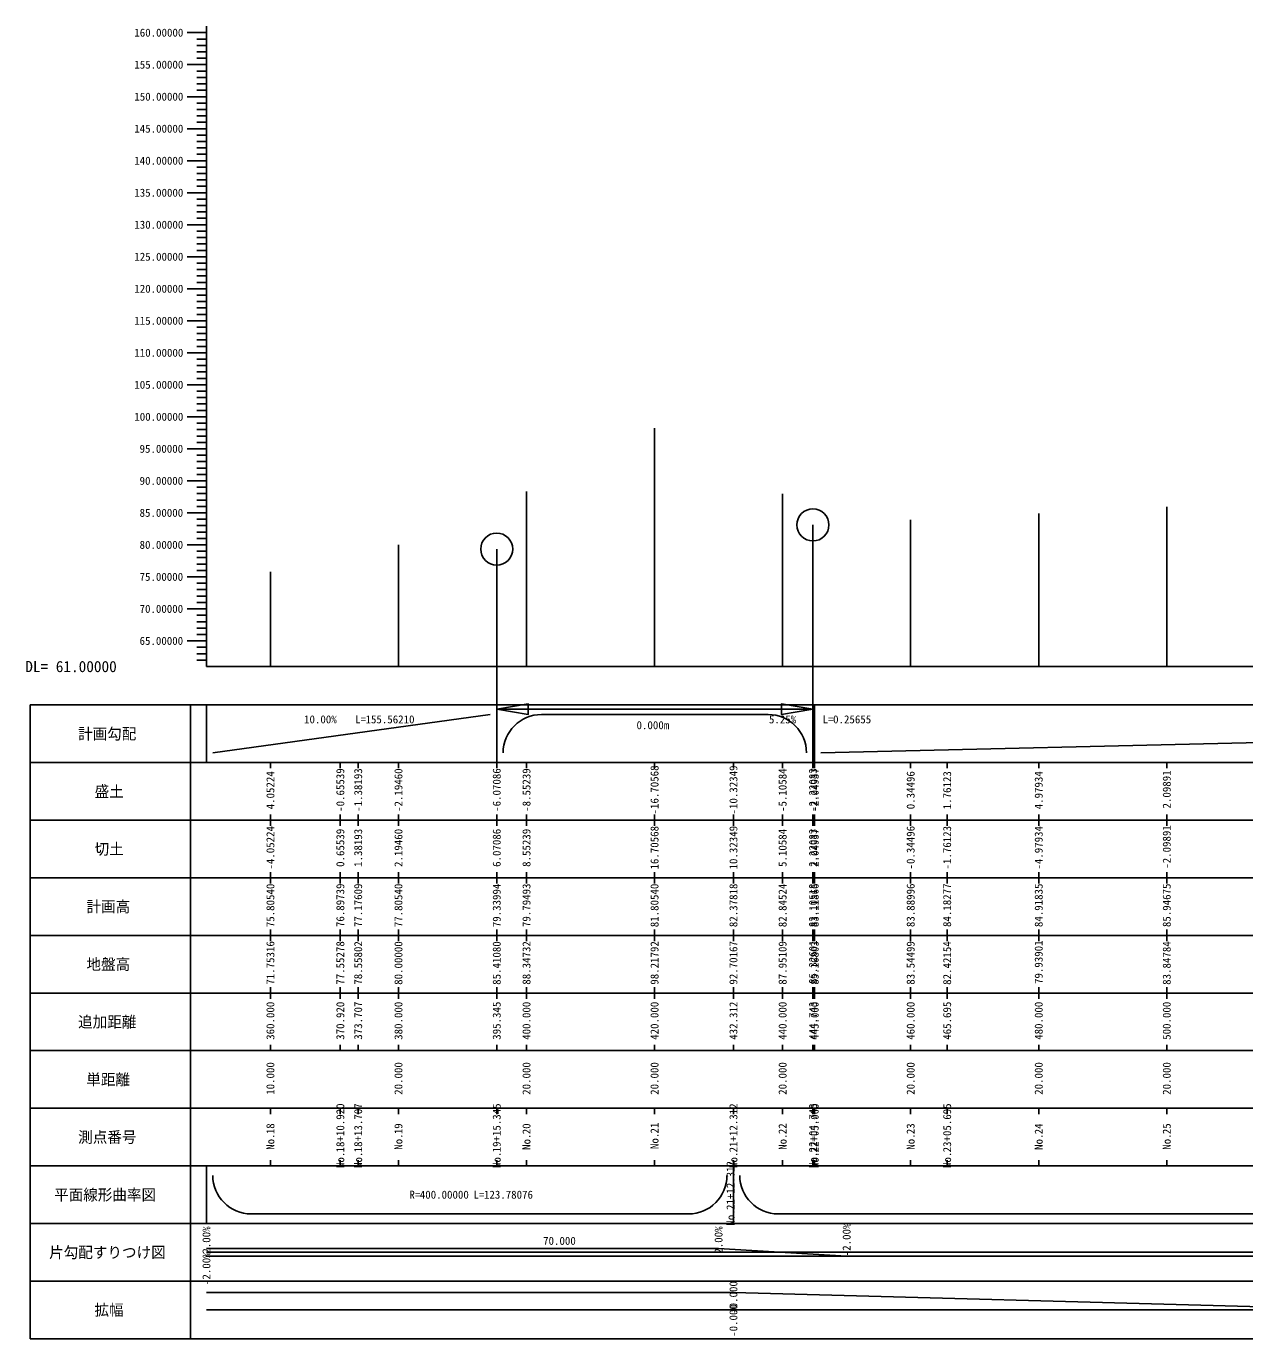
# Model space of a CAD drawing. Extents: x 322 to 703, y -44 to 161.
# Drawn here: x 321.9 to 512.2, y -44 to 161 of the extents above; entities that cross this region are included whole.
import ezdxf

# ---------------------------------------------------------------- set-up
doc = ezdxf.new("R2010")
doc.units = 0
for name, color, linetype in [('Default', 7, 'Continuous'), ('設計図面_縦断図_グリッド', 7, 'Continuous'), ('設計図面_縦断図_テキスト', 7, 'Continuous')]:
    doc.layers.add(name, color=color, linetype=linetype)

msp = doc.modelspace()

# ---------------------------------------------------------------- linework, layer by layer
at = {"layer": 'Default'}
for p, q in [((444.74, 83.11), (444.74, 54.34)), ((395.35, 79.34), (395.35, 54.34)), ((395.35, 56.84), (395.35, 51.84)), ((444.74, 51.84), (444.74, 56.84)), ((350, 55), (350, 46)), ((395.35, 55), (395.35, 46)), ((395.35, 55), (395.35, 46)), ((395.35, 54.34), (444.74, 54.34)), ((444.74, 55), (444.74, 46)), ((444.74, 55), (444.74, 46)), ((445, 55), (445, 46)), ((445, 55), (445, 46)), ((350, -17), (350, -26)), ((432.31, -17), (432.31, -26)), ((432.31, -17), (432.31, -26)), ((350, -29.9), (430, -29.9)), ((430, -29.9), (450, -31.1)), ((450, -31.1), (700, -31.1))]:
    msp.add_line(p, q, dxfattribs=at)
for points in [[(395.35, 54.34), (400.28, 55.16), (400.28, 53.52)], [(444.74, 54.34), (439.81, 53.52), (439.81, 55.16)]]:
    msp.add_lwpolyline(points, close=True, dxfattribs=at)
for centre in [(444.74, 83.11), (395.35, 79.34)]:
    msp.add_circle(centre, 2.5, dxfattribs=at)
at = {"layer": '設計図面_縦断図_グリッド'}
for p, q in [((350, 160), (347, 160)), ((350, 61), (350, 161)), ((350, 159), (348.5, 159)), ((350, 158), (348.5, 158)), ((350, 157), (348.5, 157)), ((350, 156), (348.5, 156)), ((350, 155), (347, 155)), ((350, 154), (348.5, 154)), ((350, 153), (348.5, 153)), ((350, 152), (348.5, 152)), ((350, 150), (347, 150)), ((350, 151), (348.5, 151)), ((350, 149), (348.5, 149)), ((350, 148), (348.5, 148)), ((350, 147), (348.5, 147)), ((350, 146), (348.5, 146)), ((350, 145), (347, 145)), ((350, 144), (348.5, 144)), ((350, 143), (348.5, 143)), ((350, 142), (348.5, 142)), ((350, 140), (347, 140)), ((350, 141), (348.5, 141)), ((350, 139), (348.5, 139)), ((350, 138), (348.5, 138)), ((350, 137), (348.5, 137)), ((350, 136), (348.5, 136)), ((350, 135), (347, 135)), ((350, 134), (348.5, 134)), ((350, 133), (348.5, 133)), ((350, 132), (348.5, 132)), ((350, 130), (347, 130)), ((350, 131), (348.5, 131)), ((350, 129), (348.5, 129)), ((350, 128), (348.5, 128)), ((350, 127), (348.5, 127)), ((350, 126), (348.5, 126)), ((350, 125), (347, 125)), ((350, 124), (348.5, 124)), ((350, 123), (348.5, 123)), ((350, 122), (348.5, 122)), ((350, 121), (348.5, 121)), ((350, 120), (347, 120)), ((350, 119), (348.5, 119)), ((350, 118), (348.5, 118)), ((350, 117), (348.5, 117)), ((350, 115), (347, 115)), ((350, 116), (348.5, 116)), ((350, 114), (348.5, 114)), ((350, 113), (348.5, 113)), ((350, 112), (348.5, 112)), ((350, 111), (348.5, 111)), ((350, 110), (347, 110)), ((350, 109), (348.5, 109)), ((350, 108), (348.5, 108)), ((350, 107), (348.5, 107)), ((350, 105), (347, 105)), ((350, 106), (348.5, 106)), ((350, 104), (348.5, 104)), ((350, 103), (348.5, 103)), ((350, 102), (348.5, 102)), ((350, 101), (348.5, 101)), ((350, 100), (347, 100)), ((350, 99), (348.5, 99)), ((350, 98), (348.5, 98)), ((350, 97), (348.5, 97)), ((420, 61), (420, 98.23)), ((350, 95), (347, 95)), ((350, 96), (348.5, 96)), ((350, 94), (348.5, 94)), ((350, 93), (348.5, 93)), ((350, 92), (348.5, 92)), ((350, 91), (348.5, 91)), ((350, 90), (347, 90)), ((350, 89), (348.5, 89)), ((400, 61), (400, 88.35)), ((350, 88), (348.5, 88)), ((350, 87), (348.5, 87)), ((440, 61), (440, 87.96)), ((350, 85), (347, 85)), ((350, 86), (348.5, 86)), ((480, 61), (480, 84.92)), ((500, 61), (500, 85.95)), ((350, 84), (348.5, 84)), ((350, 83), (348.5, 83)), ((350, 82), (348.5, 82)), ((460, 61), (460, 83.89)), ((350, 80), (347, 80)), ((350, 81), (348.5, 81)), ((380, 61), (380, 80)), ((350, 79), (348.5, 79)), ((350, 78), (348.5, 78)), ((350, 77), (348.5, 77)), ((350, 76), (348.5, 76)), ((350, 75), (347, 75)), ((350, 74), (348.5, 74)), ((360, 61), (360, 75.81)), ((350, 73), (348.5, 73)), ((350, 72), (348.5, 72)), ((350, 70), (347, 70)), ((350, 71), (348.5, 71)), ((350, 69), (348.5, 69)), ((350, 68), (348.5, 68)), ((350, 67), (348.5, 67)), ((350, 66), (348.5, 66)), ((350, 65), (347, 65)), ((350, 64), (348.5, 64)), ((350, 63), (348.5, 63)), ((350, 62), (348.5, 62)), ((350, 61), (700, 61)), ((322.5, 55), (322.5, 46)), ((702.5, 55), (322.5, 55)), ((347.5, 55), (347.5, 46)), ((351, 47.5), (394.35, 53.5)), ((402.35, 53.5), (437.74, 53.5)), ((446, 47.5), (699, 53.5)), ((322.5, 46), (702.5, 46)), ((322.5, 46), (322.5, 37)), ((702.5, 46), (322.5, 46)), ((347.5, 46), (347.5, 37)), ((360, 46), (360, 45.1)), ((370.92, 46), (370.92, 45.1)), ((373.71, 46), (373.71, 45.1)), ((380, 46), (380, 45.1)), ((395.35, 46), (395.35, 45.1)), ((400, 46), (400, 45.1)), ((420, 46), (420, 45.1)), ((432.31, 46), (432.31, 45.1)), ((440, 46), (440, 45.1)), ((444.74, 46), (444.74, 45.1)), ((445, 46), (445, 45.1)), ((460, 46), (460, 45.1)), ((465.69, 46), (465.69, 45.1)), ((480, 46), (480, 45.1)), ((500, 46), (500, 45.1)), ((322.5, 37), (702.5, 37)), ((322.5, 37), (322.5, 28)), ((702.5, 37), (322.5, 37)), ((347.5, 37), (347.5, 28)), ((360, 37), (360, 37.9)), ((360, 37), (360, 36.1)), ((370.92, 37), (370.92, 37.9)), ((370.92, 37), (370.92, 36.1)), ((373.71, 37), (373.71, 37.9)), ((373.71, 37), (373.71, 36.1)), ((380, 37), (380, 37.9)), ((380, 37), (380, 36.1)), ((395.35, 37), (395.35, 37.9)), ((395.35, 37), (395.35, 36.1)), ((400, 37), (400, 37.9)), ((400, 37), (400, 36.1)), ((420, 37), (420, 37.9)), ((420, 37), (420, 36.1)), ((432.31, 37), (432.31, 37.9)), ((432.31, 37), (432.31, 36.1)), ((440, 37), (440, 37.9)), ((440, 37), (440, 36.1)), ((444.74, 37), (444.74, 37.9)), ((444.74, 37), (444.74, 36.1)), ((445, 37), (445, 37.9)), ((445, 37), (445, 36.1)), ((460, 37), (460, 37.9)), ((460, 37), (460, 36.1)), ((465.69, 37), (465.69, 37.9)), ((465.69, 37), (465.69, 36.1)), ((480, 37), (480, 37.9)), ((480, 37), (480, 36.1)), ((500, 37), (500, 37.9)), ((500, 37), (500, 36.1)), ((360, 28), (360, 28.9)), ((370.92, 28), (370.92, 28.9)), ((373.71, 28), (373.71, 28.9)), ((380, 28), (380, 28.9)), ((395.35, 28), (395.35, 28.9)), ((400, 28), (400, 28.9)), ((420, 28), (420, 28.9)), ((432.31, 28), (432.31, 28.9)), ((440, 28), (440, 28.9)), ((444.74, 28), (444.74, 28.9)), ((445, 28), (445, 28.9)), ((460, 28), (460, 28.9)), ((465.69, 28), (465.69, 28.9)), ((480, 28), (480, 28.9)), ((500, 28), (500, 28.9)), ((322.5, 28), (702.5, 28)), ((322.5, 28), (322.5, 19)), ((702.5, 28), (322.5, 28)), ((347.5, 28), (347.5, 19)), ((360, 28), (360, 27.1)), ((370.92, 28), (370.92, 27.1)), ((373.71, 28), (373.71, 27.1)), ((380, 28), (380, 27.1)), ((395.35, 28), (395.35, 27.1)), ((400, 28), (400, 27.1)), ((420, 28), (420, 27.1)), ((432.31, 28), (432.31, 27.1)), ((440, 28), (440, 27.1)), ((444.74, 28), (444.74, 27.1)), ((445, 28), (445, 27.1)), ((460, 28), (460, 27.1)), ((465.69, 28), (465.69, 27.1)), ((480, 28), (480, 27.1)), ((500, 28), (500, 27.1)), ((322.5, 19), (702.5, 19)), ((322.5, 19), (322.5, 10)), ((702.5, 19), (322.5, 19)), ((347.5, 19), (347.5, 10)), ((360, 19), (360, 19.9)), ((360, 19), (360, 18.1)), ((370.92, 19), (370.92, 19.9)), ((370.92, 19), (370.92, 18.1)), ((373.71, 19), (373.71, 19.9)), ((373.71, 19), (373.71, 18.1)), ((380, 19), (380, 19.9)), ((380, 19), (380, 18.1)), ((395.35, 19), (395.35, 19.9)), ((395.35, 19), (395.35, 18.1)), ((400, 19), (400, 19.9)), ((400, 19), (400, 18.1)), ((420, 19), (420, 19.9)), ((420, 19), (420, 18.1)), ((432.31, 19), (432.31, 19.9)), ((432.31, 19), (432.31, 18.1)), ((440, 19), (440, 19.9)), ((440, 19), (440, 18.1)), ((444.74, 19), (444.74, 19.9)), ((444.74, 19), (444.74, 18.1)), ((445, 19), (445, 19.9)), ((445, 19), (445, 18.1)), ((460, 19), (460, 19.9)), ((460, 19), (460, 18.1)), ((465.69, 19), (465.69, 19.9)), ((465.69, 19), (465.69, 18.1)), ((480, 19), (480, 19.9)), ((480, 19), (480, 18.1)), ((500, 19), (500, 19.9)), ((500, 19), (500, 18.1)), ((360, 10), (360, 10.9)), ((370.92, 10), (370.92, 10.9)), ((373.71, 10), (373.71, 10.9)), ((380, 10), (380, 10.9)), ((395.35, 10), (395.35, 10.9)), ((400, 10), (400, 10.9)), ((420, 10), (420, 10.9)), ((432.31, 10), (432.31, 10.9)), ((440, 10), (440, 10.9)), ((444.74, 10), (444.74, 10.9)), ((445, 10), (445, 10.9)), ((460, 10), (460, 10.9)), ((465.69, 10), (465.69, 10.9)), ((480, 10), (480, 10.9)), ((500, 10), (500, 10.9)), ((322.5, 10), (702.5, 10)), ((322.5, 10), (322.5, 1)), ((702.5, 10), (322.5, 10)), ((347.5, 10), (347.5, 1)), ((360, 10), (360, 9.1)), ((370.92, 10), (370.92, 9.1)), ((373.71, 10), (373.71, 9.1)), ((380, 10), (380, 9.1)), ((395.35, 10), (395.35, 9.1)), ((400, 10), (400, 9.1)), ((420, 10), (420, 9.1)), ((432.31, 10), (432.31, 9.1)), ((440, 10), (440, 9.1)), ((444.74, 10), (444.74, 9.1)), ((445, 10), (445, 9.1)), ((460, 10), (460, 9.1)), ((465.69, 10), (465.69, 9.1)), ((480, 10), (480, 9.1)), ((500, 10), (500, 9.1)), ((322.5, 1), (702.5, 1)), ((322.5, 1), (322.5, -8)), ((702.5, 1), (322.5, 1)), ((347.5, 1), (347.5, -8)), ((360, 1), (360, 1.9)), ((370.92, 1), (370.92, 1.9)), ((373.71, 1), (373.71, 1.9)), ((380, 1), (380, 1.9)), ((395.35, 1), (395.35, 1.9)), ((400, 1), (400, 1.9)), ((420, 1), (420, 1.9)), ((432.31, 1), (432.31, 1.9)), ((440, 1), (440, 1.9)), ((444.74, 1), (444.74, 1.9)), ((445, 1), (445, 1.9)), ((460, 1), (460, 1.9)), ((465.69, 1), (465.69, 1.9)), ((480, 1), (480, 1.9)), ((500, 1), (500, 1.9)), ((322.5, -8), (702.5, -8)), ((322.5, -8), (322.5, -17)), ((702.5, -8), (322.5, -8)), ((347.5, -8), (347.5, -17)), ((360, -8), (360, -8.9)), ((370.92, -8), (370.92, -8.9)), ((373.71, -8), (373.71, -8.9)), ((380, -8), (380, -8.9)), ((395.35, -8), (395.35, -8.9)), ((400, -8), (400, -8.9)), ((420, -8), (420, -8.9)), ((432.31, -8), (432.31, -8.9)), ((440, -8), (440, -8.9)), ((444.74, -8), (444.74, -8.9)), ((445, -8), (445, -8.9)), ((460, -8), (460, -8.9)), ((465.69, -8), (465.69, -8.9)), ((480, -8), (480, -8.9)), ((500, -8), (500, -8.9)), ((360, -17), (360, -16.1)), ((370.92, -17), (370.92, -16.1)), ((373.71, -17), (373.71, -16.1)), ((380, -17), (380, -16.1)), ((395.35, -17), (395.35, -16.1)), ((400, -17), (400, -16.1)), ((420, -17), (420, -16.1)), ((432.31, -17), (432.31, -16.1)), ((440, -17), (440, -16.1)), ((444.74, -17), (444.74, -16.1)), ((445, -17), (445, -16.1)), ((460, -17), (460, -16.1)), ((465.69, -17), (465.69, -16.1)), ((480, -17), (480, -16.1)), ((500, -17), (500, -16.1)), ((322.5, -17), (702.5, -17)), ((322.5, -17), (322.5, -26)), ((702.5, -17), (322.5, -17)), ((347.5, -17), (347.5, -26)), ((357, -24.5), (425.31, -24.5)), ((439.31, -24.5), (531.31, -24.5)), ((322.5, -26), (702.5, -26)), ((322.5, -26), (322.5, -35)), ((702.5, -26), (322.5, -26)), ((347.5, -26), (347.5, -35)), ((350, -30.5), (700, -30.5)), ((350, -31.1), (700, -31.1)), ((322.5, -35), (702.5, -35)), ((322.5, -35), (322.5, -44)), ((702.5, -35), (322.5, -35)), ((347.5, -35), (347.5, -44)), ((350, -36.8), (432.31, -36.8)), ((432.31, -36.8), (432.31, -36.8)), ((432.31, -36.8), (532.31, -39.5)), ((350, -39.5), (700, -39.5)), ((322.5, -44), (702.5, -44))]:
    msp.add_line(p, q, dxfattribs=at)
for centre, start, end in [((402.35, 47.5), 90, 180), ((437.74, 47.5), 0, 90), ((357, -18.5), 180, 270), ((425.31, -18.5), 270, 0), ((439.31, -18.5), 180, 270)]:
    msp.add_arc(centre, 6, start, end, dxfattribs=at)

# ---------------------------------------------------------------- texts
at = {"layer": 'Default'}
msp.add_text('0.000m', height=1.25, dxfattribs=at).set_placement((417.19, 51.21))
at = {"layer": '設計図面_縦断図_テキスト'}
for s, height, p in [('160.00000', 1.25, (338.75, 159.38)), ('155.00000', 1.25, (338.75, 154.38)), ('150.00000', 1.25, (338.75, 149.38)), ('145.00000', 1.25, (338.75, 144.38)), ('140.00000', 1.25, (338.75, 139.38)), ('135.00000', 1.25, (338.75, 134.38)), ('130.00000', 1.25, (338.75, 129.38)), ('125.00000', 1.25, (338.75, 124.38)), ('120.00000', 1.25, (338.75, 119.38)), ('115.00000', 1.25, (338.75, 114.38)), ('110.00000', 1.25, (338.75, 109.38)), ('105.00000', 1.25, (338.75, 104.38)), ('100.00000', 1.25, (338.75, 99.38)), ('95.00000', 1.25, (339.57, 94.38)), ('90.00000', 1.25, (339.57, 89.38)), ('85.00000', 1.25, (339.57, 84.38)), ('80.00000', 1.25, (339.57, 79.38)), ('75.00000', 1.25, (339.57, 74.38)), ('70.00000', 1.25, (339.57, 69.38)), ('65.00000', 1.25, (339.57, 64.38)), ('DL= 61.00000', 1.75, (321.72, 60.12)), ('10.00%', 1.25, (365.26, 52.12)), ('L=', 1.25, (373.24, 52.12)), ('155.56210', 1.25, (374.86, 52.12)), ('5.25%', 1.25, (437.87, 52.12)), ('L=', 1.25, (446.26, 52.12)), ('0.25655', 1.25, (447.89, 52.12)), ('計画勾配', 1.75, (329.96, 49.62)), ('盛土', 1.75, (332.55, 40.62)), ('切土', 1.75, (332.55, 31.62)), ('計画高', 1.75, (331.27, 22.62)), ('地盤高', 1.75, (331.27, 13.62)), ('追加距離', 1.75, (329.97, 4.62)), ('単距離', 1.75, (331.25, -4.38)), ('測点番号', 1.75, (329.98, -13.38)), ('平面線形曲率図', 1.75, (326.22, -22.38)), ('R=', 1.25, (381.72, -22.12)), ('400.00000', 1.25, (383.34, -22.12)), ('L=', 1.25, (391.73, -22.12)), ('123.78076', 1.25, (393.36, -22.12)), ('70.000', 1.25, (402.6, -29.33)), ('片勾配すりつけ図', 1.75, (325.45, -31.38)), ('拡幅', 1.75, (332.52, -40.38))]:
    msp.add_text(s, height=height, dxfattribs=at).set_placement(p)
for s, p in [('-16.70568', (420.62, 37.89)), ('-10.32349', (432.94, 37.89)), ('4.05224', (360.62, 38.69)), ('-0.65539', (371.54, 38.3)), ('-1.38193', (374.33, 38.3)), ('-2.19460', (380.62, 38.28)), ('-6.07086', (395.97, 38.3)), ('-8.55239', (400.62, 38.3)), ('-5.10584', (440.62, 38.28)), ('-2.22083', (445.37, 38.3)), ('-2.04937', (445.63, 38.31)), ('0.34496', (460.62, 38.7)), ('1.76123', (466.32, 38.7)), ('4.97934', (480.62, 38.69)), ('2.09891', (500.62, 38.82)), ('-4.05224', (360.62, 29.28)), ('0.65539', (371.54, 29.7)), ('1.38193', (374.33, 29.7)), ('2.19460', (380.62, 29.69)), ('6.07086', (395.97, 29.7)), ('8.55239', (400.62, 29.7)), ('16.70568', (420.62, 29.29)), ('10.32349', (432.94, 29.3)), ('5.10584', (440.62, 29.69)), ('2.22083', (445.37, 29.7)), ('2.04937', (445.63, 29.71)), ('-0.34496', (460.62, 29.3)), ('-1.76123', (466.32, 29.3)), ('-4.97934', (480.62, 29.28)), ('-2.09891', (500.62, 29.41)), ('75.80540', (360.62, 20.28)), ('76.89739', (371.54, 20.3)), ('77.17609', (374.33, 20.3)), ('77.80540', (380.62, 20.28)), ('79.33994', (395.97, 20.28)), ('79.79493', (400.62, 20.3)), ('81.80540', (420.62, 20.28)), ('82.37818', (432.94, 20.29)), ('82.84524', (440.62, 20.28)), ('83.10518', (445.37, 20.29)), ('83.11866', (445.63, 20.3)), ('83.88996', (460.62, 20.3)), ('84.18277', (466.32, 20.31)), ('84.91835', (480.62, 20.3)), ('85.94675', (500.62, 20.3)), ('71.75316', (360.62, 11.3)), ('77.55278', (371.54, 11.29)), ('78.55802', (374.33, 11.3)), ('80.00000', (380.62, 11.28)), ('85.41080', (395.97, 11.28)), ('88.34732', (400.62, 11.3)), ('98.21792', (420.62, 11.3)), ('92.70167', (432.94, 11.31)), ('87.95109', (440.62, 11.3)), ('85.32601', (445.37, 11.41)), ('85.16803', (445.63, 11.3)), ('83.54499', (460.62, 11.3)), ('82.42154', (466.32, 11.28)), ('79.93901', (480.62, 11.41)), ('83.84784', (500.62, 11.28)), ('360.000', (360.62, 2.69)), ('370.920', (371.54, 2.69)), ('373.707', (374.33, 2.71)), ('380.000', (380.62, 2.69)), ('395.345', (395.97, 2.7)), ('400.000', (400.62, 2.69)), ('420.000', (420.62, 2.69)), ('432.312', (432.94, 2.7)), ('440.000', (440.62, 2.69)), ('444.743', (445.37, 2.7)), ('445.000', (445.63, 2.69)), ('460.000', (460.62, 2.69)), ('465.695', (466.32, 2.7)), ('480.000', (480.62, 2.69)), ('500.000', (500.62, 2.69)), ('10.000', (360.62, -5.9)), ('20.000', (380.62, -5.9)), ('20.000', (400.62, -5.9)), ('20.000', (420.62, -5.9)), ('20.000', (440.62, -5.9)), ('20.000', (460.62, -5.9)), ('20.000', (480.62, -5.9)), ('20.000', (500.62, -5.9)), ('18+10.920', (371.54, -14.9)), ('18+13.707', (374.33, -14.88)), ('19+15.345', (395.97, -14.89)), ('21+12.312', (432.94, -14.89)), ('22+04.743', (445.37, -14.89)), ('22+05.000', (445.63, -14.9)), ('23+05.695', (466.32, -14.89)), ('No.', (360.62, -14.49)), ('18', (360.62, -12.05)), ('No.', (380.62, -14.48)), ('19', (380.62, -12.05)), ('No.', (400.62, -14.5)), ('20', (400.62, -12.06)), ('No.', (420.62, -14.37)), ('21', (420.62, -11.94)), ('No.', (440.62, -14.49)), ('22', (440.62, -12.05)), ('No.', (460.62, -14.48)), ('23', (460.62, -12.05)), ('No.', (480.62, -14.5)), ('24', (480.62, -12.07)), ('No.', (500.62, -14.48)), ('25', (500.62, -12.05)), ('No.', (371.54, -17.34)), ('No.', (374.33, -17.32)), ('No.', (395.97, -17.33)), ('21+12.312', (432.49, -23.89)), ('No.', (432.94, -17.33)), ('No.', (445.37, -17.33)), ('No.', (445.63, -17.34)), ('No.', (466.32, -17.33)), ('No.', (432.49, -26.33)), ('2.00%', (350.63, -30.71)), ('2.00%', (430.62, -30.71)), ('-2.00%', (450.62, -31.11)), ('-2.00%', (350.63, -35.61)), ('-0.000', (432.94, -40.1)), ('-0.000', (432.94, -40.1)), ('-0.000', (432.94, -43.7)), ('-0.000', (432.94, -43.7))]:
    msp.add_text(s, height=1.25, rotation=90, dxfattribs=at).set_placement(p)

doc.saveas('drawing.dxf')
